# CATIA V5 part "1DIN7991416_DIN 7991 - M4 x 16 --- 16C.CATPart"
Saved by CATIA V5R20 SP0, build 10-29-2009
Part number: 1DIN7991416_DIN 7991 - M4 x 16 --- 16C
Revision: ANY
Definition: UNKNOWN
Nomenclature: 1DIN7991416_DIN 7991 - M4 x 16 --- 16C
Source: Unknown
Bounding box of the stored display mesh (mm): x 0 to 16, y -3.633 to 3.633, z -3.82 to 3.82
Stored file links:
  C:\Users\Utente\Desktop\IO LAVORO\3D X SITO CF\CUMSA\3D files PW\pw060630\pw060630_ejection\1DIN7991416_DIN 7991 - M4 x 16 --- 16C.CATPart
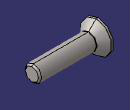
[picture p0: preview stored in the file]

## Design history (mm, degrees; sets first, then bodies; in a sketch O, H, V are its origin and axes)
Body1 "Hex" (main body)
  Solid1: solid without history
